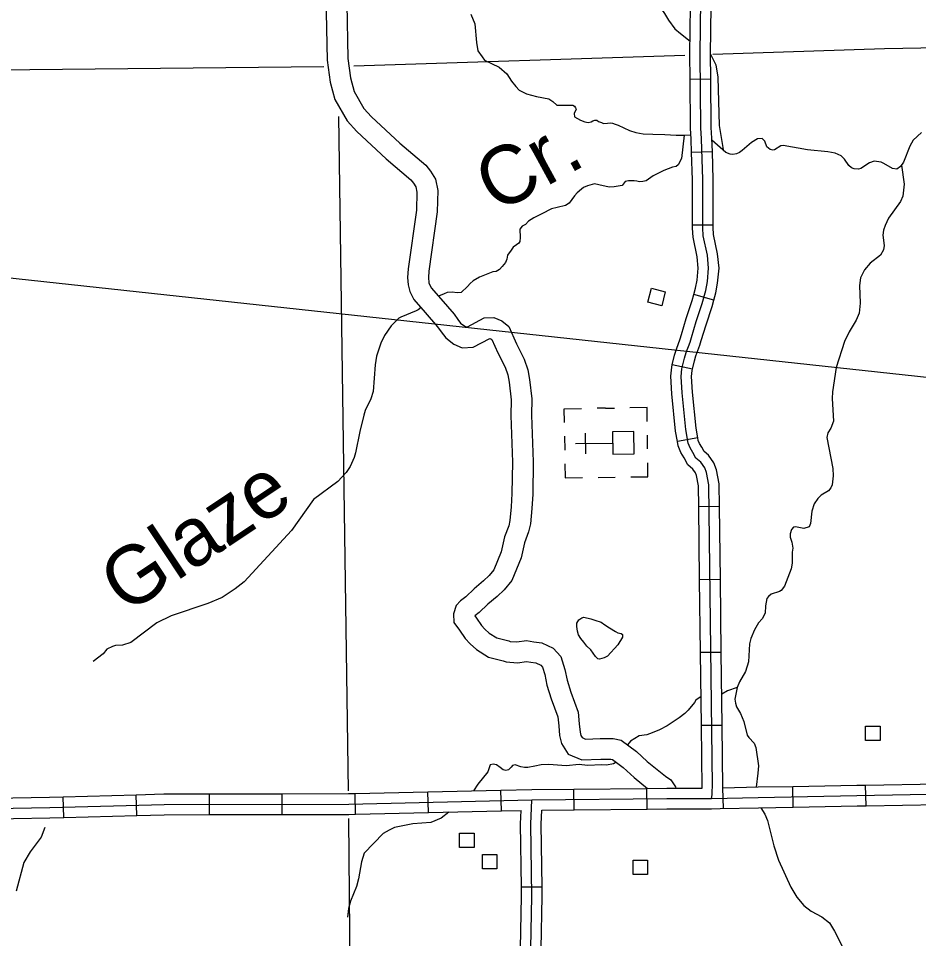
# Model space of a CAD drawing. Extents: x 1369885 to 1370219, y 379980 to 380218.
# Drawn here: x 1370079.7 to 1370105.62, y 380081.59 to 380108.07 of the extents above; entities that cross this region are included whole.
import ezdxf

# ---------------------------------------------------------------- set-up
doc = ezdxf.new("R2010")
doc.units = 0
for name, color, linetype in [('Level 32', 7, 'Continuous'), ('Level 35', 7, 'Continuous'), ('Level 46', 7, 'Continuous'), ('Level 5', 7, 'Continuous'), ('Level 56', 7, 'Continuous'), ('Level 57', 7, 'Continuous'), ('Page Text', 7, 'Continuous')]:
    doc.layers.add(name, color=color, linetype=linetype)

msp = doc.modelspace()

# ---------------------------------------------------------------- linework, layer by layer
at = {"layer": 'Level 32'}
for p, q in [((1370099.634, 380106.315), (1370099.037, 380106.312)), ((1370099.678, 380104.224), (1370099.082, 380104.205)), ((1370099.706, 380102.115), (1370099.109, 380102.114)), ((1370099.722, 380099.964), (1370099.146, 380100.118)), ((1370099.105, 380097.97), (1370098.523, 380098.102)), ((1370099.261, 380096.002), (1370098.673, 380095.896)), ((1370099.883, 380094.024), (1370099.286, 380094.016)), ((1370099.909, 380091.924), (1370099.312, 380091.916)), ((1370099.935, 380089.824), (1370099.338, 380089.816)), ((1370099.961, 380087.723), (1370099.365, 380087.716)), ((1370095.699, 380085.295), (1370095.694, 380085.891)), ((1370097.799, 380085.313), (1370097.794, 380085.909)), ((1370099.997, 380085.331), (1370099.984, 380085.928)), ((1370102.002, 380085.371), (1370101.991, 380085.968)), ((1370104.102, 380085.409), (1370104.091, 380086.006)), ((1370081.005, 380085.073), (1370080.989, 380085.669)), ((1370083.105, 380085.131), (1370083.088, 380085.727)), ((1370085.197, 380085.155), (1370085.196, 380085.751)), ((1370087.297, 380085.158), (1370087.296, 380085.755)), ((1370089.404, 380085.166), (1370089.39, 380085.762)), ((1370091.504, 380085.215), (1370091.49, 380085.811)), ((1370093.603, 380085.264), (1370093.589, 380085.86)), ((1370094.775, 380083.07), (1370094.179, 380083.063))]:
    msp.add_line(p, q, dxfattribs=at)
for points in [[(1370099.037, 380098.754), (1370099.073, 380098.885), (1370099.211, 380099.343), (1370099.386, 380099.863), (1370099.486, 380100.237), (1370099.534, 380100.493), (1370099.57, 380100.877), (1370099.535, 380101.25), (1370099.418, 380101.813), (1370099.407, 380102.04), (1370099.406, 380103.431), (1370099.367, 380104.606), (1370099.344, 380104.92), (1370099.331, 380107.04), (1370099.354, 380109.38)], [(1370099.037, 380106.312), (1370099.033, 380107.041), (1370099.046, 380108.417)], [(1370099.634, 380106.315), (1370099.629, 380107.04), (1370099.643, 380108.411)], [(1370099.082, 380104.205), (1370099.069, 380104.59), (1370099.045, 380104.908), (1370099.037, 380106.312)], [(1370099.678, 380104.224), (1370099.665, 380104.622), (1370099.642, 380104.932), (1370099.634, 380106.315)], [(1370099.109, 380102.114), (1370099.107, 380103.426), (1370099.082, 380104.205)], [(1370099.706, 380102.115), (1370099.704, 380103.436), (1370099.678, 380104.224)], [(1370099.146, 380100.118), (1370099.195, 380100.302), (1370099.238, 380100.534), (1370099.27, 380100.877), (1370099.239, 380101.206), (1370099.121, 380101.775), (1370099.109, 380102.033), (1370099.109, 380102.114)], [(1370099.722, 380099.964), (1370099.777, 380100.171), (1370099.83, 380100.452), (1370099.87, 380100.877), (1370099.83, 380101.295), (1370099.715, 380101.851), (1370099.706, 380102.047), (1370099.706, 380102.115)], [(1370098.523, 380098.102), (1370098.585, 380098.374), (1370098.643, 380098.554), (1370098.753, 380098.847), (1370098.787, 380098.968), (1370098.927, 380099.434), (1370099.1, 380099.949), (1370099.146, 380100.118)], [(1370099.105, 380097.97), (1370099.161, 380098.216), (1370099.206, 380098.358), (1370099.321, 380098.661), (1370099.36, 380098.802), (1370099.496, 380099.253), (1370099.672, 380099.777), (1370099.722, 380099.964)], [(1370099.652, 380085.622), (1370099.674, 380085.721), (1370099.677, 380085.812), (1370099.685, 380085.988), (1370099.576, 380094.647), (1370099.51, 380094.999), (1370099.458, 380095.133), (1370099.342, 380095.297), (1370099.207, 380095.415), (1370099.119, 380095.576), (1370099.037, 380095.707), (1370098.985, 380095.847), (1370098.915, 380096.236), (1370098.806, 380097.288), (1370098.782, 380097.765), (1370098.803, 380097.987), (1370098.873, 380098.295), (1370098.925, 380098.456), (1370099.037, 380098.754)], [(1370098.673, 380095.896), (1370098.62, 380096.194), (1370098.508, 380097.265), (1370098.483, 380097.772), (1370098.508, 380098.035), (1370098.523, 380098.102)], [(1370099.261, 380096.002), (1370099.211, 380096.278), (1370099.104, 380097.311), (1370099.081, 380097.759), (1370099.098, 380097.94), (1370099.105, 380097.97)], [(1370099.883, 380094.024), (1370099.874, 380094.676), (1370099.798, 380095.081), (1370099.723, 380095.276), (1370099.565, 380095.499), (1370099.443, 380095.605), (1370099.377, 380095.727), (1370099.306, 380095.839), (1370099.274, 380095.925), (1370099.261, 380096.002)], [(1370099.286, 380094.016), (1370099.278, 380094.617), (1370099.222, 380094.917), (1370099.193, 380094.991), (1370099.119, 380095.096), (1370098.971, 380095.225), (1370098.862, 380095.425), (1370098.768, 380095.574), (1370098.696, 380095.768), (1370098.673, 380095.896)], [(1370099.312, 380091.916), (1370099.286, 380094.016)], [(1370099.909, 380091.924), (1370099.883, 380094.024)], [(1370099.338, 380089.816), (1370099.312, 380091.916)], [(1370099.935, 380089.824), (1370099.909, 380091.924)], [(1370099.365, 380087.716), (1370099.338, 380089.816)], [(1370099.961, 380087.723), (1370099.935, 380089.824)], [(1370099.387, 380085.919), (1370099.365, 380087.716)], [(1370099.984, 380085.928), (1370099.961, 380087.723)], [(1370093.589, 380085.86), (1370094.48, 380085.881), (1370095.694, 380085.891)], [(1370095.694, 380085.891), (1370097.794, 380085.909)], [(1370097.794, 380085.909), (1370098.366, 380085.914), (1370099.387, 380085.919)], [(1370099.984, 380085.928), (1370100.994, 380085.95), (1370101.991, 380085.968)], [(1370101.991, 380085.968), (1370103.837, 380086.001), (1370104.091, 380086.006)], [(1370104.091, 380086.006), (1370106.191, 380086.044)], [(1370071.512, 380083.132), (1370071.609, 380083.223), (1370071.777, 380083.299), (1370071.915, 380083.339), (1370072.33, 380083.35), (1370072.524, 380083.387), (1370072.67, 380083.46), (1370072.797, 380083.575), (1370073.027, 380083.829), (1370073.227, 380084.102), (1370073.347, 380084.319), (1370073.688, 380084.909), (1370073.773, 380085.075), (1370073.833, 380085.142), (1370073.894, 380085.214), (1370074.009, 380085.257), (1370077.649, 380085.292), (1370079.547, 380085.342), (1370080.601, 380085.36), (1370083.893, 380085.451), (1370089.208, 380085.459), (1370094.485, 380085.583), (1370098.368, 380085.616), (1370099.652, 380085.622)], [(1370078.889, 380085.623), (1370079.54, 380085.64), (1370080.595, 380085.658), (1370080.989, 380085.669)], [(1370080.989, 380085.669), (1370083.088, 380085.727)], [(1370083.088, 380085.727), (1370083.888, 380085.749), (1370085.196, 380085.751)], [(1370085.196, 380085.751), (1370087.296, 380085.755)], [(1370087.296, 380085.755), (1370089.204, 380085.758), (1370089.39, 380085.762)], [(1370089.39, 380085.762), (1370091.49, 380085.811)], [(1370091.49, 380085.811), (1370093.589, 380085.86)], [(1370099.652, 380085.622), (1370101, 380085.651), (1370103.842, 380085.703), (1370108.454, 380085.787)], [(1370094.688, 380064.166), (1370094.631, 380068.558), (1370094.552, 380074.13), (1370094.498, 380076.007), (1370094.469, 380080.042), (1370094.454, 380081.298), (1370094.48, 380082.808), (1370094.456, 380084.887), (1370094.47, 380085.344), (1370094.485, 380085.583)], [(1370099.903, 380085.329), (1370101.006, 380085.353), (1370102.002, 380085.371)], [(1370102.002, 380085.371), (1370103.847, 380085.404), (1370104.102, 380085.409)], [(1370104.102, 380085.409), (1370106.202, 380085.448)], [(1370081.005, 380085.073), (1370083.105, 380085.131)], [(1370083.105, 380085.131), (1370083.897, 380085.153), (1370085.197, 380085.155)], [(1370085.197, 380085.155), (1370087.297, 380085.158)], [(1370087.297, 380085.158), (1370089.211, 380085.161), (1370089.404, 380085.166)], [(1370089.404, 380085.166), (1370091.504, 380085.215)], [(1370091.504, 380085.215), (1370093.603, 380085.264)], [(1370093.603, 380085.264), (1370094.17, 380085.277)], [(1370094.179, 380083.063), (1370094.158, 380084.89), (1370094.17, 380085.277)], [(1370094.775, 380083.07), (1370094.754, 380084.884), (1370094.767, 380085.287)], [(1370094.767, 380085.287), (1370095.699, 380085.295)], [(1370095.699, 380085.295), (1370097.799, 380085.313)], [(1370097.799, 380085.313), (1370098.37, 380085.318), (1370099.656, 380085.324), (1370099.903, 380085.329)], [(1370078.905, 380085.027), (1370079.553, 380085.043), (1370080.608, 380085.062), (1370081.005, 380085.073)], [(1370094.16, 380080.963), (1370094.156, 380081.299), (1370094.181, 380082.808), (1370094.179, 380083.063)], [(1370094.757, 380080.97), (1370094.753, 380081.297), (1370094.778, 380082.807), (1370094.775, 380083.07)]]:
    msp.add_lwpolyline(points, dxfattribs=at)
at = {"layer": 'Level 35'}
msp.add_line((1370082.139, 380089.784), (1370081.848, 380089.564), dxfattribs=at)
for points in [[(1370097.316, 380110.08), (1370097.339, 380109.834), (1370097.381, 380109.652), (1370097.433, 380109.498), (1370097.551, 380109.282), (1370097.659, 380109.13), (1370097.935, 380108.745), (1370098.304, 380108.205), (1370098.42, 380108.017), (1370098.602, 380107.769), (1370098.762, 380107.636), (1370099.036, 380107.416)], [(1370092.723, 380108.193), (1370092.84, 380107.913), (1370092.884, 380107.378), (1370092.925, 380107.133), (1370093.049, 380106.964), (1370093.116, 380106.867), (1370093.545, 380106.666), (1370093.76, 380106.473)], [(1370099.629, 380107.037), (1370099.775, 380106.733), (1370099.833, 380106.38), (1370099.879, 380104.987), (1370099.924, 380104.701), (1370099.985, 380104.297)], [(1370093.76, 380106.473), (1370093.893, 380106.264), (1370094.02, 380106.104), (1370094.113, 380105.999), (1370094.323, 380105.894), (1370094.615, 380105.817), (1370094.974, 380105.75), (1370095.089, 380105.676), (1370095.197, 380105.571), (1370095.439, 380105.567), (1370095.536, 380105.574), (1370095.657, 380105.568), (1370095.712, 380105.541), (1370095.74, 380105.499), (1370095.756, 380105.458), (1370095.704, 380105.331), (1370095.707, 380105.237), (1370095.792, 380105.19), (1370095.881, 380105.135), (1370096.005, 380105.094), (1370096.101, 380105.072), (1370096.192, 380105.094), (1370096.239, 380105.121), (1370096.297, 380105.144), (1370096.352, 380105.144), (1370096.404, 380105.105), (1370096.482, 380105.075), (1370096.545, 380105.047), (1370096.658, 380105.05), (1370096.741, 380105.061), (1370096.801, 380105.055), (1370096.881, 380105.028), (1370096.97, 380104.991), (1370097.296, 380104.846), (1370097.473, 380104.787), (1370097.688, 380104.744), (1370097.964, 380104.741), (1370098.306, 380104.73), (1370098.634, 380104.705), (1370098.867, 380104.71), (1370099.06, 380104.714)], [(1370098.867, 380104.71), (1370098.793, 380104.037), (1370098.693, 380103.851), (1370098.641, 380103.808), (1370098.535, 380103.788), (1370098.281, 380103.692), (1370097.976, 380103.539), (1370097.773, 380103.393), (1370097.679, 380103.371), (1370097.581, 380103.365), (1370097.504, 380103.388), (1370097.43, 380103.392), (1370097.261, 380103.394), (1370097.172, 380103.37), (1370097.084, 380103.26), (1370096.967, 380103.242), (1370096.848, 380103.222), (1370096.704, 380103.21), (1370096.412, 380103.276), (1370096.282, 380103.308), (1370096.081, 380103.249), (1370095.964, 380103.197), (1370095.909, 380103.152), (1370095.788, 380103.045), (1370095.709, 380102.964), (1370095.551, 380102.75), (1370095.45, 380102.683), (1370095.207, 380102.63), (1370095.051, 380102.588), (1370094.768, 380102.443), (1370094.537, 380102.327), (1370094.381, 380102.234), (1370094.3, 380102.136), (1370094.202, 380102.086), (1370094.135, 380102.003), (1370094.141, 380101.761), (1370094.135, 380101.645), (1370094.102, 380101.595), (1370094.04, 380101.554), (1370093.948, 380101.488), (1370093.882, 380101.402), (1370093.782, 380101.25)], [(1370105.703, 380104.786), (1370105.464, 380104.56), (1370105.362, 380104.393), (1370105.185, 380103.933), (1370105.098, 380103.803), (1370104.993, 380103.732), (1370104.869, 380103.744), (1370104.614, 380103.896), (1370104.534, 380103.926), (1370104.334, 380103.955), (1370104.201, 380103.907), (1370103.951, 380103.752), (1370103.881, 380103.73), (1370103.765, 380103.735), (1370103.685, 380103.764), (1370103.611, 380103.83), (1370103.486, 380104.017), (1370103.384, 380104.114), (1370103.215, 380104.188), (1370103.003, 380104.23), (1370102.422, 380104.284), (1370101.719, 380104.41), (1370101.652, 380104.4), (1370101.464, 380104.287), (1370101.417, 380104.277), (1370101.341, 380104.295), (1370101.243, 380104.376), (1370101.187, 380104.533), (1370101.109, 380104.611), (1370100.974, 380104.603), (1370100.807, 380104.494), (1370100.54, 380104.265)], [(1370100.54, 380104.265), (1370100.458, 380104.207), (1370100.371, 380104.17), (1370100.266, 380104.148), (1370100.189, 380104.159), (1370100.069, 380104.205), (1370099.667, 380104.568)], [(1370105.128, 380103.848), (1370105.197, 380103.296), (1370105.163, 380102.956), (1370105.096, 380102.803), (1370104.754, 380102.318), (1370104.649, 380102.111), (1370104.605, 380101.974), (1370104.59, 380101.834), (1370104.627, 380101.529), (1370104.606, 380101.408), (1370104.52, 380101.258), (1370104.221, 380101.026), (1370104.06, 380100.83), (1370103.948, 380100.599), (1370103.911, 380100.379), (1370103.938, 380099.877), (1370103.907, 380099.585), (1370103.822, 380099.384), (1370103.614, 380099.05), (1370103.483, 380098.771), (1370103.244, 380098.023), (1370103.138, 380097.322), (1370103.128, 380097.126), (1370103.167, 380096.482), (1370103.09, 380096.272), (1370102.999, 380096.138), (1370102.975, 380096.009), (1370103.145, 380095.118), (1370103.155, 380094.907), (1370103.124, 380094.647), (1370103.091, 380094.558), (1370103.026, 380094.468), (1370102.815, 380094.346), (1370102.711, 380094.256), (1370102.608, 380094.097), (1370102.543, 380093.892), (1370102.502, 380093.536), (1370102.465, 380093.439), (1370102.316, 380093.386), (1370102.076, 380093.439), (1370102.017, 380093.425), (1370101.955, 380093.364), (1370101.923, 380093.239), (1370101.922, 380093.143), (1370101.97, 380092.997), (1370101.995, 380092.827), (1370101.975, 380092.706), (1370101.977, 380092.388), (1370101.946, 380092.227), (1370101.754, 380091.731), (1370101.659, 380091.605), (1370101.612, 380091.571), (1370101.372, 380091.496), (1370101.291, 380091.434), (1370101.249, 380091.373), (1370101.207, 380091.168), (1370101.198, 380090.953), (1370101.108, 380090.791), (1370101.008, 380090.676), (1370100.887, 380090.477), (1370100.783, 380090.223), (1370100.752, 380090.066), (1370100.716, 380089.547), (1370100.633, 380089.277)], [(1370093.782, 380101.25), (1370093.763, 380101.14), (1370093.727, 380101.041), (1370093.628, 380100.925), (1370093.553, 380100.843), (1370093.452, 380100.785), (1370093.358, 380100.779), (1370092.972, 380100.624), (1370092.795, 380100.514), (1370092.707, 380100.436), (1370092.63, 380100.354), (1370092.443, 380100.177), (1370092.332, 380100.172), (1370092.189, 380100.188), (1370092.04, 380100.177), (1370091.952, 380100.144), (1370091.796, 380100.075)], [(1370091.29, 380099.745), (1370091.209, 380099.686), (1370091.15, 380099.657), (1370090.707, 380099.472), (1370090.648, 380099.438), (1370090.432, 380099.22), (1370090.242, 380098.939), (1370090.134, 380098.721), (1370090.01, 380098.346), (1370089.966, 380098.094), (1370089.914, 380097.335), (1370089.845, 380097.118), (1370089.684, 380096.786), (1370089.64, 380096.649), (1370089.524, 380096.183), (1370089.407, 380095.566), (1370089.368, 380095.433), (1370089.248, 380095.17), (1370089.138, 380094.999), (1370088.896, 380094.745), (1370088.193, 380094.221), (1370087.564, 380093.329), (1370086.199, 380091.857), (1370085.939, 380091.65), (1370085.561, 380091.407), (1370085.15, 380091.227), (1370084.096, 380090.88), (1370083.685, 380090.676), (1370082.931, 380090.111), (1370082.695, 380090.036), (1370082.493, 380090.026), (1370082.406, 380089.996), (1370082.242, 380089.919), (1370082.139, 380089.784)], [(1370095.89, 380090.219), (1370095.823, 380090.328), (1370095.798, 380090.438), (1370095.774, 380090.572), (1370095.774, 380090.663), (1370095.832, 380090.76), (1370095.92, 380090.821), (1370095.981, 380090.833), (1370096.182, 380090.791), (1370096.291, 380090.754), (1370096.48, 380090.69)], [(1370096.48, 380090.69), (1370096.583, 380090.614), (1370096.717, 380090.529), (1370096.893, 380090.426), (1370096.954, 380090.389), (1370097.057, 380090.365), (1370097.088, 380090.334), (1370097.094, 380090.261), (1370096.96, 380090.042), (1370096.662, 380089.714), (1370096.565, 380089.671), (1370096.425, 380089.628), (1370096.382, 380089.641), (1370096.309, 380089.708), (1370096.176, 380089.896), (1370096.066, 380090), (1370095.975, 380090.121), (1370095.89, 380090.219)], [(1370100.633, 380089.277), (1370100.46, 380088.977), (1370100.389, 380088.812), (1370100.328, 380088.475), (1370100.343, 380088.36), (1370100.37, 380088.261), (1370100.487, 380088.069), (1370100.582, 380087.837), (1370100.685, 380087.437), (1370100.727, 380087.371), (1370100.883, 380087.212), (1370100.926, 380087.09), (1370101.002, 380086.558), (1370100.992, 380086.351), (1370100.936, 380085.948)], [(1370100.389, 380088.812), (1370100.114, 380088.72), (1370099.95, 380088.618)], [(1370099.354, 380088.556), (1370099.198, 380088.448), (1370099.161, 380088.381), (1370098.985, 380088.162), (1370098.883, 380088.063), (1370098.724, 380087.943), (1370098.377, 380087.706), (1370098.154, 380087.596), (1370097.945, 380087.511), (1370097.791, 380087.453), (1370097.567, 380087.426), (1370097.319, 380087.268), (1370097.233, 380087.168)], [(1370094.968, 380086.595), (1370094.745, 380086.589), (1370094.566, 380086.55), (1370094.369, 380086.514), (1370094.271, 380086.507), (1370094.162, 380086.534), (1370094, 380086.587), (1370093.927, 380086.572), (1370093.887, 380086.518), (1370093.811, 380086.442), (1370093.732, 380086.424), (1370093.659, 380086.445), (1370093.569, 380086.514), (1370093.46, 380086.583), (1370093.369, 380086.608), (1370093.282, 380086.583), (1370093.216, 380086.391), (1370092.922, 380086.03), (1370092.798, 380085.842)], [(1370096.913, 380086.662), (1370096.829, 380086.62), (1370096.632, 380086.582), (1370096.492, 380086.585), (1370096.087, 380086.573), (1370095.845, 380086.598), (1370095.472, 380086.563), (1370094.968, 380086.595)], [(1370101.07, 380085.354), (1370101.187, 380085.165), (1370101.268, 380084.984), (1370101.449, 380084.26), (1370101.585, 380083.845), (1370101.938, 380083.063), (1370102.114, 380082.781), (1370102.316, 380082.536), (1370102.519, 380082.375), (1370102.83, 380082.217), (1370103.054, 380082.04), (1370103.196, 380081.801), (1370103.602, 380081.001)], [(1370092.094, 380085.228), (1370091.866, 380085.052), (1370091.573, 380084.928), (1370091.053, 380084.887), (1370090.528, 380084.787), (1370090.369, 380084.704), (1370090.199, 380084.611), (1370089.658, 380084.049), (1370089.574, 380083.796), (1370089.486, 380083.303), (1370089.429, 380083.086), (1370089.259, 380082.666), (1370089.202, 380082.449), (1370089.174, 380082.205)], [(1370080.463, 380084.783), (1370080.353, 380084.504), (1370080.036, 380084.088), (1370079.858, 380083.78), (1370079.637, 380082.956)]]:
    msp.add_lwpolyline(points, dxfattribs=at)
at = {"layer": 'Level 46'}
for points in [[(1370088.525, 380110.088), (1370088.586, 380106.87), (1370088.677, 380106.236), (1370088.808, 380105.735), (1370089.16, 380105.116), (1370089.446, 380104.817), (1370090.283, 380104.03), (1370090.998, 380103.423), (1370091.078, 380103.325), (1370091.141, 380103.219), (1370091.171, 380103.069), (1370091.158, 380102.548), (1370090.925, 380100.859), (1370090.905, 380100.615), (1370090.917, 380100.405), (1370090.968, 380100.208)], [(1370089.122, 380110.067), (1370089.182, 380106.918), (1370089.263, 380106.354), (1370089.366, 380105.962), (1370089.643, 380105.475), (1370089.866, 380105.24), (1370090.681, 380104.475), (1370091.426, 380103.843), (1370091.568, 380103.668), (1370091.706, 380103.437), (1370091.77, 380103.12), (1370091.754, 380102.5), (1370091.518, 380100.794), (1370091.503, 380100.607), (1370091.512, 380100.455)], [(1370091.512, 380100.455), (1370091.583, 380100.313), (1370091.86, 380100.001), (1370092.243, 380099.559), (1370092.35, 380099.403), (1370092.429, 380099.301), (1370092.551, 380099.209), (1370092.592, 380099.189), (1370092.627, 380099.191), (1370093.11, 380099.449), (1370093.386, 380099.461), (1370093.613, 380099.364), (1370093.817, 380099.202), (1370094.038, 380098.705), (1370094.263, 380098.266), (1370094.368, 380097.956), (1370094.417, 380097.681), (1370094.481, 380097.117), (1370094.472, 380096.649), (1370094.517, 380095.305), (1370094.505, 380094.378), (1370094.48, 380093.966), (1370094.441, 380093.527), (1370094.386, 380093.292), (1370094.266, 380092.98), (1370094.173, 380092.544), (1370093.902, 380091.888), (1370093.685, 380091.624), (1370093.484, 380091.436), (1370093.217, 380091.207), (1370092.966, 380090.97), (1370092.838, 380090.874), (1370092.884, 380090.811), (1370093.03, 380090.601), (1370093.129, 380090.496), (1370093.255, 380090.381), (1370093.475, 380090.239), (1370093.815, 380090.155), (1370093.861, 380090.14), (1370094.049, 380090.123), (1370094.327, 380090.163), (1370094.539, 380090.132), (1370094.77, 380090.098), (1370095.091, 380089.946), (1370095.318, 380089.709), (1370095.435, 380089.334), (1370095.494, 380089.026), (1370095.604, 380088.683), (1370095.813, 380088.107), (1370095.848, 380087.765), (1370095.87, 380087.527), (1370095.891, 380087.432), (1370095.929, 380087.373), (1370096.029, 380087.331), (1370096.45, 380087.35), (1370096.819, 380087.35), (1370097.057, 380087.3), (1370097.493, 380086.974), (1370097.804, 380086.684)], [(1370090.968, 380100.208), (1370091.085, 380099.976), (1370091.412, 380099.608), (1370091.769, 380099.195), (1370091.867, 380099.051), (1370092.007, 380098.873), (1370092.238, 380098.697), (1370092.476, 380098.583), (1370092.795, 380098.605), (1370093.271, 380098.859), (1370093.276, 380098.859), (1370093.304, 380098.847), (1370093.331, 380098.825), (1370093.499, 380098.447), (1370093.712, 380098.033), (1370093.789, 380097.808), (1370093.826, 380097.596), (1370093.883, 380097.089), (1370093.875, 380096.645), (1370093.92, 380095.299), (1370093.908, 380094.4), (1370093.884, 380094.01), (1370093.85, 380093.621), (1370093.814, 380093.468), (1370093.692, 380093.151), (1370093.6, 380092.721), (1370093.385, 380092.198), (1370093.249, 380092.034), (1370093.085, 380091.881), (1370092.817, 380091.65), (1370092.581, 380091.427), (1370092.425, 380091.31), (1370092.3, 380091.17), (1370092.223, 380090.932), (1370092.238, 380090.687), (1370092.397, 380090.466), (1370092.566, 380090.222), (1370092.71, 380090.071), (1370092.889, 380089.907), (1370093.235, 380089.684), (1370093.654, 380089.58), (1370093.742, 380089.552), (1370094.064, 380089.522), (1370094.326, 380089.56), (1370094.451, 380089.541), (1370094.596, 380089.52), (1370094.737, 380089.453), (1370094.79, 380089.398), (1370094.855, 380089.189), (1370094.914, 380088.879), (1370095.039, 380088.49), (1370095.227, 380087.973), (1370095.254, 380087.707), (1370095.28, 380087.434), (1370095.331, 380087.2), (1370095.525, 380086.894), (1370095.923, 380086.729), (1370096.463, 380086.753), (1370096.757, 380086.753), (1370096.805, 380086.743), (1370097.111, 380086.515), (1370097.429, 380086.219)], [(1370097.804, 380086.684), (1370098.333, 380086.257), (1370098.487, 380086.152), (1370098.621, 380085.95), (1370098.629, 380085.916)], [(1370097.429, 380086.219), (1370097.813, 380085.91)]]:
    msp.add_lwpolyline(points, dxfattribs=at)
at = {"layer": 'Level 5'}
for points in [[(1370109.345, 380107.275), (1370104.636, 380107.193), (1370099.688, 380107.03)], [(1370098.89, 380107.004), (1370089.354, 380106.69)], [(1370088.494, 380106.671), (1370068.72, 380106.473)], [(1370088.912, 380105.244), (1370089.197, 380085.842)], [(1370089.207, 380085.042), (1370089.317, 380071.905)]]:
    msp.add_lwpolyline(points, dxfattribs=at)
at = {"layer": 'Level 56'}
for points in [[(1370097.817, 380099.9), (1370097.922, 380100.301), (1370098.323, 380100.196), (1370098.219, 380099.795)], [(1370104.09, 380087.285), (1370104.09, 380087.699), (1370104.505, 380087.699), (1370104.505, 380087.285)], [(1370092.401, 380084.206), (1370092.401, 380084.62), (1370092.816, 380084.62), (1370092.816, 380084.206)], [(1370093.059, 380083.594), (1370093.059, 380084.008), (1370093.474, 380084.008), (1370093.474, 380083.594)], [(1370097.4, 380083.432), (1370097.4, 380083.846), (1370097.815, 380083.846), (1370097.815, 380083.432)]]:
    msp.add_lwpolyline(points, close=True, dxfattribs=at)
at = {"layer": 'Level 57'}
for p, q in [((1370096.606, 380096.852), (1370096.361, 380096.849)), ((1370096.606, 380096.852), (1370096.858, 380096.855)), ((1370095.423, 380096.043), (1370095.429, 380095.645)), ((1370096.037, 380095.54), (1370096.029, 380096.136)), ((1370097.815, 380095.677), (1370097.81, 380096.074)), ((1370095.734, 380095.834), (1370096.805, 380095.848)), ((1370096.387, 380094.86), (1370096.884, 380094.867))]:
    msp.add_line(p, q, dxfattribs=at)
for points in [[(1370095.418, 380096.439), (1370095.413, 380096.836), (1370095.91, 380096.843)], [(1370097.805, 380096.47), (1370097.799, 380096.868), (1370097.302, 380096.861)], [(1370095.434, 380095.245), (1370095.439, 380094.848), (1370095.936, 380094.854)], [(1370097.328, 380094.872), (1370097.825, 380094.879), (1370097.82, 380095.277)]]:
    msp.add_lwpolyline(points, dxfattribs=at)
msp.add_lwpolyline([(1370097.422, 380096.177), (1370096.801, 380096.169), (1370096.81, 380095.525), (1370097.43, 380095.533)], close=True, dxfattribs=at)
at = {"layer": 'Page Text'}
msp.add_lwpolyline([(1370047.12, 380104.1), (1370131.535, 380094.962)], dxfattribs=at)

# ---------------------------------------------------------------- texts
at = {"layer": 'Level 35'}
for s, rotation, p in [('Cr.', 28.6764, (1370093.46, 380102.439)), ('Glaze', 33.6309, (1370082.794, 380090.892))]:
    msp.add_text(s, height=1.6802, rotation=rotation, dxfattribs=at).set_placement(p)

doc.saveas('drawing.dxf')
